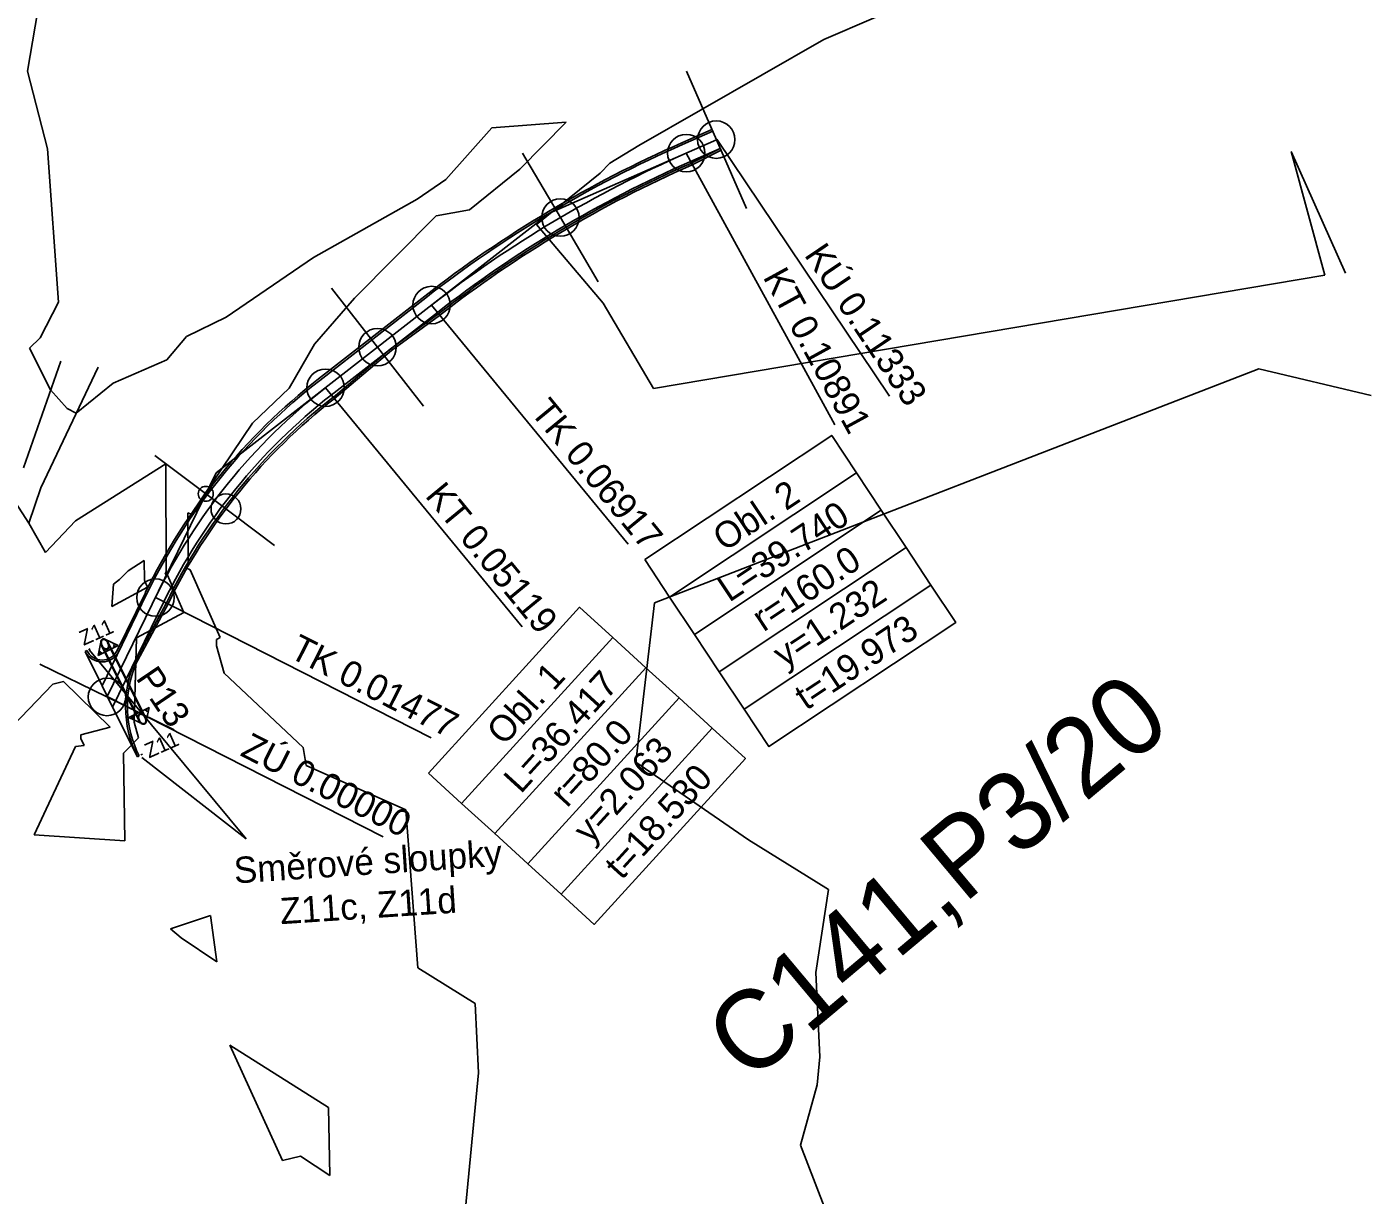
# Model space of a CAD drawing. Extents: x -549394 to -546608, y -1037055 to -1033629.
# Drawn here: x -547399.4 to -547219.7, y -1035351 to -1035194.8 of the extents above; entities that cross this region are included whole.
import ezdxf

# ---------------------------------------------------------------- set-up
doc = ezdxf.new("R2010")
doc.units = 0
for name, color, linetype in [('hlavni_vrst', 7, 'Continuous'), ('hrana_L', 7, 'Continuous'), ('norm_vrst', 7, 'Continuous'), ('POLYGONY_SITUACE_PO', 7, 'Continuous'), ('u_sirka_1_0m', 7, 'Continuous'), ('u_sirka_1_5m', 7, 'Continuous'), ('x_navrh_C141', 7, 'Continuous'), ('x_osa_C141', 7, 'Continuous'), ('x_popis_C141', 7, 'Continuous'), ('x_popis_oblouky_C141', 7, 'Continuous'), ('x_popis_pricne_rezy_C141', 7, 'Continuous'), ('x_popis_velky_C141', 7, 'Continuous'), ('x_propustek', 7, 'Continuous'), ('x_SDZ_C141', 7, 'Continuous')]:
    doc.layers.add(name, color=color, linetype=linetype)

msp = doc.modelspace()

# ---------------------------------------------------------------- linework, layer by layer
at = {"layer": 'hlavni_vrst'}
for p, q in [((-547292.9, -1035196.54), (-547278.84, -1035190.47)), ((-547317.64, -1035210.67), (-547292.9, -1035196.54)), ((-547321.49, -1035213.06), (-547317.64, -1035210.67)), ((-547230.43, -1035211.49), (-547225.89, -1035228.02)), ((-547223.15, -1035227.75), (-547230.43, -1035211.49)), ((-547322.82, -1035214.4), (-547321.49, -1035213.06)), ((-547331.31, -1035221.25), (-547322.82, -1035214.4)), ((-547322.39, -1035231.75), (-547331.31, -1035221.25)), ((-547225.89, -1035228.02), (-547315.67, -1035243.17)), ((-547315.67, -1035243.17), (-547322.39, -1035231.75)), ((-547315.53, -1035271.79), (-547234.74, -1035240.52)), ((-547234.74, -1035240.52), (-547219.72, -1035244.12)), ((-547318.05, -1035293.1), (-547315.53, -1035271.79)), ((-547302.95, -1035303.47), (-547318.05, -1035293.1)), ((-547292.27, -1035310.1), (-547302.95, -1035303.47)), ((-547293.96, -1035321.23), (-547292.27, -1035310.1)), ((-547293.45, -1035332.48), (-547293.96, -1035321.23)), ((-547293.8, -1035336.21), (-547293.45, -1035332.48)), ((-547296, -1035344.28), (-547293.8, -1035336.21)), ((-547283.79, -1035376.04), (-547296, -1035344.28))]:
    msp.add_line(p, q, dxfattribs=at)
at = {"layer": 'hrana_L'}
for p, q in [((-547394.93, -1035239.52), (-547399.91, -1035253.77)), ((-547389.94, -1035240.31), (-547397.57, -1035256.44)), ((-547397.57, -1035256.44), (-547399.19, -1035261.16))]:
    msp.add_line(p, q, dxfattribs=at)
at = {"layer": 'norm_vrst'}
for p, q in [((-547399.36, -1035200.76), (-547397.01, -1035186.98)), ((-547396.7, -1035211.13), (-547399.36, -1035200.76)), ((-547337.3, -1035208.32), (-547343.44, -1035215.22)), ((-547327.34, -1035207.57), (-547337.3, -1035208.32)), ((-547333.56, -1035213.85), (-547327.34, -1035207.57)), ((-547395.23, -1035231.65), (-547396.7, -1035211.13)), ((-547340.29, -1035219.28), (-547333.56, -1035213.85)), ((-547343.44, -1035215.22), (-547347.28, -1035217.87)), ((-547347.28, -1035217.87), (-547361.11, -1035225.68)), ((-547344.71, -1035220.1), (-547340.29, -1035219.28)), ((-547355.64, -1035231.11), (-547344.71, -1035220.1)), ((-547361.11, -1035225.68), (-547372.79, -1035233.63)), ((-547397.67, -1035236.39), (-547395.23, -1035231.65)), ((-547361.01, -1035237.24), (-547355.64, -1035231.11)), ((-547372.79, -1035233.63), (-547378.1, -1035236.22)), ((-547399.08, -1035237.78), (-547397.67, -1035236.39)), ((-547378.1, -1035236.22), (-547380.73, -1035239.35)), ((-547364.39, -1035243.11), (-547361.01, -1035237.24)), ((-547396.27, -1035243.34), (-547399.08, -1035237.78)), ((-547380.73, -1035239.35), (-547387.91, -1035242.46)), ((-547387.91, -1035242.46), (-547392.85, -1035246.47)), ((-547394.05, -1035245.85), (-547396.27, -1035243.34)), ((-547369.28, -1035247.8), (-547364.39, -1035243.11)), ((-547392.85, -1035246.47), (-547394.05, -1035245.85)), ((-547377.5, -1035259.97), (-547369.28, -1035247.8)), ((-547380.88, -1035253.24), (-547392.94, -1035260.85)), ((-547380.81, -1035267.64), (-547380.88, -1035253.24)), ((-547399.19, -1035261.16), (-547402.86, -1035255.5)), ((-547392.94, -1035260.85), (-547396.98, -1035265.09)), ((-547377.89, -1035266.54), (-547377.92, -1035259.76)), ((-547377.92, -1035259.76), (-547377.5, -1035259.97)), ((-547399.19, -1035261.16), (-547399.19, -1035261.16)), ((-547399.19, -1035261.16), (-547399.19, -1035261.16)), ((-547396.98, -1035265.09), (-547399.19, -1035261.16)), ((-547399.19, -1035261.16), (-547399.19, -1035261.16)), ((-547383.75, -1035266.15), (-547385.92, -1035267.52)), ((-547383.74, -1035268.75), (-547383.75, -1035266.15)), ((-547385.92, -1035267.52), (-547387.06, -1035268.71)), ((-547380.97, -1035267.96), (-547380.81, -1035267.64)), ((-547380.66, -1035268.12), (-547380.97, -1035267.96)), ((-547378.46, -1035273.09), (-547380.66, -1035268.12)), ((-547378.18, -1035267.11), (-547377.89, -1035266.54)), ((-547377.61, -1035267.4), (-547378.18, -1035267.11)), ((-547373.61, -1035276.45), (-547377.61, -1035267.4)), ((-547387.88, -1035269.32), (-547388.08, -1035272.29)), ((-547388.08, -1035272.29), (-547383.31, -1035269.73)), ((-547387.06, -1035268.71), (-547387.88, -1035269.32)), ((-547383.77, -1035268.8), (-547383.74, -1035268.75)), ((-547383.71, -1035268.83), (-547383.77, -1035268.8)), ((-547383.31, -1035269.73), (-547383.71, -1035268.83)), ((-547384.79, -1035276.49), (-547378.46, -1035273.09)), ((-547385.1, -1035287.74), (-547384.79, -1035276.49)), ((-547374.1, -1035277.54), (-547374.08, -1035276.7)), ((-547374.08, -1035276.7), (-547373.61, -1035276.45)), ((-547373.07, -1035281.22), (-547374.1, -1035277.54)), ((-547395.97, -1035282.66), (-547394.56, -1035282.33)), ((-547394.56, -1035282.33), (-547388.3, -1035288.42)), ((-547362.51, -1035291.15), (-547373.07, -1035281.22)), ((-547404.2, -1035291.19), (-547395.97, -1035282.66)), ((-547384.51, -1035289.83), (-547385.1, -1035287.74)), ((-547388.3, -1035288.42), (-547392.24, -1035289.43)), ((-547392.24, -1035289.43), (-547392.22, -1035289.95)), ((-547392.94, -1035290.99), (-547398.47, -1035302.8)), ((-547391.81, -1035290.88), (-547392.94, -1035290.99)), ((-547392.22, -1035289.95), (-547391.81, -1035290.88)), ((-547386.51, -1035291.88), (-547384.51, -1035289.83)), ((-547362.1, -1035293.55), (-547362.51, -1035291.15)), ((-547386.34, -1035303.6), (-547386.51, -1035291.88)), ((-547348.8, -1035299.47), (-547362.1, -1035293.55)), ((-547347.19, -1035320.57), (-547348.8, -1035299.47)), ((-547398.47, -1035302.8), (-547386.34, -1035303.6)), ((-547374.89, -1035313.57), (-547380.23, -1035315.38)), ((-547374.05, -1035319.8), (-547374.89, -1035313.57)), ((-547380.23, -1035315.38), (-547378.83, -1035316.58)), ((-547378.83, -1035316.58), (-547374.05, -1035319.8)), ((-547339.51, -1035325.35), (-547347.19, -1035320.57)), ((-547339.08, -1035334.62), (-547339.51, -1035325.35)), ((-547372.31, -1035330.92), (-547359.1, -1035339.24)), ((-547365.27, -1035346.33), (-547372.31, -1035330.92)), ((-547341.62, -1035361.33), (-547339.08, -1035334.62)), ((-547359.1, -1035339.24), (-547358.95, -1035348.33)), ((-547362.88, -1035345.77), (-547365.27, -1035346.33)), ((-547365.27, -1035346.33), (-547365.27, -1035346.33)), ((-547358.95, -1035348.33), (-547362.88, -1035345.77)), ((-547362.88, -1035345.77), (-547362.88, -1035345.77))]:
    msp.add_line(p, q, dxfattribs=at)
at = {"layer": 'POLYGONY_SITUACE_PO'}
for centre in [(-547307.28, -1035209.91), (-547311.29, -1035211.71), (-547345.34, -1035232.01), (-547359.52, -1035243.06), (-547382.26, -1035271.11), (-547388.74, -1035284.39)]:
    msp.add_circle(centre, 2.5, dxfattribs=at)
at = {"layer": 'u_sirka_1_0m'}
for centre in [(-547328.12, -1035220.32), (-547352.57, -1035237.65)]:
    msp.add_circle(centre, 2.5, dxfattribs=at)
at = {"layer": 'u_sirka_1_5m'}
for centre, radius in [((-547375.53, -1035257.24), 1), ((-547372.83, -1035259.26), 2)]:
    msp.add_circle(centre, radius, dxfattribs=at)
at = {"layer": 'x_navrh_C141'}
for p, q in [((-547311.9, -1035210.34), (-547307.85, -1035208.56)), ((-547311.8, -1035210.57), (-547307.75, -1035208.79)), ((-547310.79, -1035212.86), (-547306.75, -1035211.08)), ((-547310.7, -1035213.08), (-547306.75, -1035211.08)), ((-547310.59, -1035213.3), (-547306.64, -1035211.31)), ((-547360.45, -1035241.88), (-547346.26, -1035230.83)), ((-547360.29, -1035242.08), (-547346.11, -1035231.03)), ((-547358.76, -1035244.05), (-547344.57, -1035233)), ((-547344.42, -1035233.19), (-547350.87, -1035237.9)), ((-547344.27, -1035233.39), (-547350.71, -1035238.1)), ((-547358.52, -1035244.35), (-547350.87, -1035237.9)), ((-547358.36, -1035244.54), (-547350.71, -1035238.1)), ((-547389.4, -1035282.89), (-547383.39, -1035270.56)), ((-547388, -1035285.73), (-547381.14, -1035271.66)), ((-547387.38, -1035278.18), (-547383.61, -1035270.45)), ((-547380.8, -1035271.82), (-547385.52, -1035280.64)), ((-547380.57, -1035271.94), (-547381.77, -1035274.18)), ((-547381.77, -1035274.18), (-547384.91, -1035280.04)), ((-547391.42, -1035278.19), (-547391.65, -1035278.3)), ((-547391.65, -1035278.3), (-547389.4, -1035282.89)), ((-547389.4, -1035282.89), (-547388, -1035285.73)), ((-547384.67, -1035292.37), (-547384.44, -1035292.26))]:
    msp.add_line(p, q, dxfattribs=at)
msp.add_lwpolyline([(-547388, -1035285.73), (-547384.67, -1035292.37)], dxfattribs=at)
for centre, radius, start, end in [((-547247, -1035358.23), 161.5, 113.6926, 127.9233), ((-547247, -1035358.23), 161.25, 113.6926, 127.9233), ((-547247, -1035358.23), 158.75, 113.6926, 127.9233), ((-547247, -1035358.23), 158.51, 113.6926, 127.9233), ((-547247, -1035358.23), 158.26, 113.6901, 127.9246), ((-547310.36, -1035306.17), 81.5, 127.9233, 154.0053), ((-547310.36, -1035306.17), 81.25, 127.9233, 154.0053), ((-547310.36, -1035306.17), 78.75, 127.9233, 154.0053), ((-547310.36, -1035306.17), 78.37, 127.9233, 154.0053), ((-547310.36, -1035306.17), 78.12, 127.9198, 154.0088), ((-547389.4, -1035277.2), 2.5, 206.1096, 334.0053), ((-547389.4, -1035277.2), 2.25, 206.1096, 334.0053), ((-547371.26, -1035285.63), 15, 154.0053, 206.694), ((-547371.26, -1035285.63), 14.75, 157.7223, 206.694)]:
    msp.add_arc(centre, radius, start, end, dxfattribs=at)
at = {"layer": 'x_osa_C141'}
for points in [[(-547329.58, -1035219.74), (-547307.25, -1035209.94)], [(-547374.14, -1035254.45), (-547329.58, -1035219.74)], [(-547388.7, -1035284.31), (-547374.14, -1035254.45)]]:
    msp.add_lwpolyline(points, dxfattribs=at)
for centre, radius, start, end in [((-547247, -1035358.23), 160, 113.6926, 127.9233), ((-547310.36, -1035306.17), 80, 127.9233, 154.0053)]:
    msp.add_arc(centre, radius, start, end, dxfattribs=at)
at = {"layer": 'x_popis_oblouky_C141'}
for points in [[(-547284.12, -1035244.19), (-547307.21, -1035209.86)], [(-547291.44, -1035248.01), (-547311.29, -1035211.71)], [(-547319.06, -1035263.97), (-547345.34, -1035232.01)], [(-547333.24, -1035275.02), (-547359.52, -1035243.06)], [(-547345.39, -1035289.87), (-547382.26, -1035271.11)], [(-547351.82, -1035303.07), (-547388.7, -1035284.31)]]:
    msp.add_lwpolyline(points, dxfattribs=at)
for points in [[(-547316.83, -1035266.03), (-547291.84, -1035249.44), (-547288.52, -1035254.43), (-547313.52, -1035271.03)], [(-547313.52, -1035271.03), (-547288.52, -1035254.43), (-547285.21, -1035259.43), (-547310.2, -1035276.03)], [(-547310.2, -1035276.03), (-547285.21, -1035259.43), (-547281.89, -1035264.43), (-547306.88, -1035281.03)], [(-547306.88, -1035281.03), (-547281.89, -1035264.43), (-547278.57, -1035269.43), (-547303.56, -1035286.03)], [(-547303.56, -1035286.03), (-547278.57, -1035269.43), (-547275.25, -1035274.43), (-547300.24, -1035291.02)], [(-547345.76, -1035294.57), (-547325.55, -1035272.4), (-547321.12, -1035276.44), (-547341.33, -1035298.61)], [(-547341.33, -1035298.61), (-547321.12, -1035276.44), (-547316.68, -1035280.48), (-547336.89, -1035302.65)], [(-547336.89, -1035302.65), (-547316.68, -1035280.48), (-547312.25, -1035284.52), (-547332.46, -1035306.7)], [(-547332.46, -1035306.7), (-547312.25, -1035284.52), (-547307.81, -1035288.57), (-547328.02, -1035310.74)], [(-547328.02, -1035310.74), (-547307.81, -1035288.57), (-547303.38, -1035292.61), (-547323.59, -1035314.78)]]:
    msp.add_lwpolyline(points, close=True, dxfattribs=at)
at = {"layer": 'x_popis_pricne_rezy_C141'}
for points in [[(-547311.27, -1035200.78), (-547307.25, -1035209.94), (-547303.23, -1035219.09)], [(-547333.19, -1035211.7), (-547328.12, -1035220.32), (-547323.05, -1035228.93)], [(-547358.72, -1035229.76), (-547352.57, -1035237.65), (-547346.43, -1035245.54)], [(-547382.33, -1035252.13), (-547374.33, -1035258.14), (-547366.33, -1035264.14)], [(-547397.72, -1035280), (-547388.74, -1035284.39), (-547379.75, -1035288.77)]]:
    msp.add_lwpolyline(points, dxfattribs=at)
at = {"layer": 'x_propustek'}
for p, q in [((-547389.94, -1035278.85), (-547389.51, -1035276.82)), ((-547389.13, -1035276.63), (-547389.51, -1035276.82)), ((-547389.13, -1035276.63), (-547387.26, -1035277.51)), ((-547383.66, -1035287.15), (-547388.65, -1035277.15)), ((-547383.59, -1035287.11), (-547388.58, -1035277.11)), ((-547389.94, -1035278.85), (-547387.26, -1035277.51)), ((-547389.52, -1035278.64), (-547389.69, -1035278.28)), ((-547389.61, -1035278.68), (-547389.69, -1035278.5)), ((-547389.43, -1035278.59), (-547389.52, -1035278.42)), ((-547384.47, -1035287.55), (-547389.46, -1035277.55)), ((-547384.4, -1035287.52), (-547389.39, -1035277.52)), ((-547387.68, -1035277.72), (-547387.86, -1035277.36)), ((-547387.77, -1035277.77), (-547387.86, -1035277.59)), ((-547387.59, -1035277.68), (-547387.68, -1035277.5)), ((-547383.11, -1035285.81), (-547385.8, -1035287.15)), ((-547383.62, -1035286.07), (-547383.53, -1035286.25)), ((-547383.11, -1035285.81), (-547383.54, -1035287.84)), ((-547383.53, -1035286.02), (-547383.36, -1035286.38)), ((-547383.44, -1035285.98), (-547383.36, -1035286.16)), ((-547383.92, -1035288.03), (-547385.8, -1035287.15)), ((-547385.46, -1035286.99), (-547385.37, -1035287.17)), ((-547385.37, -1035286.94), (-547385.2, -1035287.3)), ((-547385.28, -1035286.9), (-547385.19, -1035287.08)), ((-547383.92, -1035288.03), (-547383.54, -1035287.84))]:
    msp.add_line(p, q, dxfattribs=at)
for points in [[(-547389.36, -1035276.66), (-547389.37, -1035276.67), (-547389.38, -1035276.67), (-547389.41, -1035276.69), (-547389.42, -1035276.7), (-547389.46, -1035276.74), (-547389.48, -1035276.76), (-547389.53, -1035276.85), (-547389.56, -1035276.92), (-547389.58, -1035277.09), (-547389.57, -1035277.18), (-547389.53, -1035277.37), (-547389.5, -1035277.46), (-547389.41, -1035277.64), (-547389.36, -1035277.72), (-547389.23, -1035277.86), (-547389.16, -1035277.92), (-547389.01, -1035278.01), (-547388.94, -1035278.03), (-547388.86, -1035278.04), (-547388.84, -1035278.04), (-547388.81, -1035278.04), (-547388.79, -1035278.04), (-547388.74, -1035278.03), (-547388.71, -1035278.02), (-547388.68, -1035278)], [(-547389.32, -1035276.73), (-547389.34, -1035276.74), (-547389.36, -1035276.75), (-547389.4, -1035276.79), (-547389.42, -1035276.81), (-547389.45, -1035276.85), (-547389.46, -1035276.88), (-547389.48, -1035276.94), (-547389.49, -1035276.98), (-547389.5, -1035277.05), (-547389.5, -1035277.09), (-547389.49, -1035277.17), (-547389.49, -1035277.22), (-547389.46, -1035277.34), (-547389.43, -1035277.43), (-547389.35, -1035277.6), (-547389.3, -1035277.68), (-547389.21, -1035277.78), (-547389.18, -1035277.81), (-547389.11, -1035277.86), (-547389.08, -1035277.88), (-547389.02, -1035277.92), (-547388.99, -1035277.93), (-547388.92, -1035277.95), (-547388.89, -1035277.96), (-547388.84, -1035277.97), (-547388.81, -1035277.96), (-547388.76, -1035277.96), (-547388.74, -1035277.95), (-547388.7, -1035277.93), (-547388.68, -1035277.91), (-547388.64, -1035277.88), (-547388.62, -1035277.86), (-547388.59, -1035277.81), (-547388.58, -1035277.78), (-547388.56, -1035277.72), (-547388.55, -1035277.69), (-547388.54, -1035277.61), (-547388.54, -1035277.57), (-547388.55, -1035277.49), (-547388.55, -1035277.45), (-547388.58, -1035277.32), (-547388.61, -1035277.23), (-547388.69, -1035277.06), (-547388.75, -1035276.99), (-547388.83, -1035276.89), (-547388.86, -1035276.86), (-547388.93, -1035276.81), (-547388.96, -1035276.78), (-547389.02, -1035276.75), (-547389.06, -1035276.73), (-547389.12, -1035276.71), (-547389.15, -1035276.7), (-547389.2, -1035276.7), (-547389.23, -1035276.7), (-547389.28, -1035276.71), (-547389.3, -1035276.72), (-547389.32, -1035276.73)], [(-547388.68, -1035278), (-547388.67, -1035278), (-547388.66, -1035277.99), (-547388.63, -1035277.97), (-547388.62, -1035277.96), (-547388.58, -1035277.93), (-547388.56, -1035277.9), (-547388.51, -1035277.81), (-547388.49, -1035277.74), (-547388.46, -1035277.57), (-547388.47, -1035277.48), (-547388.51, -1035277.3), (-547388.54, -1035277.2), (-547388.63, -1035277.02), (-547388.68, -1035276.94), (-547388.81, -1035276.8), (-547388.88, -1035276.74), (-547389.03, -1035276.66), (-547389.1, -1035276.63), (-547389.18, -1035276.63), (-547389.2, -1035276.62), (-547389.23, -1035276.63), (-547389.25, -1035276.63), (-547389.3, -1035276.64), (-547389.33, -1035276.65), (-547389.36, -1035276.66)], [(-547384.37, -1035286.66), (-547384.38, -1035286.67), (-547384.39, -1035286.67), (-547384.42, -1035286.69), (-547384.43, -1035286.7), (-547384.47, -1035286.73), (-547384.49, -1035286.76), (-547384.54, -1035286.85), (-547384.57, -1035286.92), (-547384.59, -1035287.09), (-547384.58, -1035287.18), (-547384.54, -1035287.36), (-547384.51, -1035287.46), (-547384.42, -1035287.64), (-547384.37, -1035287.72), (-547384.24, -1035287.86), (-547384.17, -1035287.92), (-547384.02, -1035288.01), (-547383.95, -1035288.03), (-547383.87, -1035288.04), (-547383.85, -1035288.04), (-547383.82, -1035288.04), (-547383.8, -1035288.04), (-547383.75, -1035288.03), (-547383.72, -1035288.02), (-547383.69, -1035288)], [(-547383.73, -1035287.94), (-547383.71, -1035287.93), (-547383.69, -1035287.91), (-547383.65, -1035287.88), (-547383.63, -1035287.86), (-547383.6, -1035287.81), (-547383.59, -1035287.78), (-547383.57, -1035287.72), (-547383.56, -1035287.69), (-547383.55, -1035287.61), (-547383.55, -1035287.57), (-547383.56, -1035287.49), (-547383.56, -1035287.45), (-547383.59, -1035287.32), (-547383.62, -1035287.23), (-547383.7, -1035287.06), (-547383.75, -1035286.98), (-547383.84, -1035286.89), (-547383.87, -1035286.86), (-547383.94, -1035286.81), (-547383.97, -1035286.78), (-547384.03, -1035286.75), (-547384.07, -1035286.73), (-547384.13, -1035286.71), (-547384.16, -1035286.7), (-547384.21, -1035286.7), (-547384.24, -1035286.7), (-547384.29, -1035286.71), (-547384.31, -1035286.71), (-547384.35, -1035286.74), (-547384.37, -1035286.75), (-547384.41, -1035286.78), (-547384.43, -1035286.8), (-547384.46, -1035286.85), (-547384.47, -1035286.88), (-547384.49, -1035286.94), (-547384.5, -1035286.98), (-547384.51, -1035287.05), (-547384.51, -1035287.09), (-547384.5, -1035287.17), (-547384.5, -1035287.21), (-547384.47, -1035287.34), (-547384.44, -1035287.43), (-547384.36, -1035287.6), (-547384.31, -1035287.68), (-547384.22, -1035287.77), (-547384.19, -1035287.8), (-547384.12, -1035287.86), (-547384.09, -1035287.88), (-547384.03, -1035287.92), (-547383.99, -1035287.93), (-547383.93, -1035287.95), (-547383.9, -1035287.96), (-547383.85, -1035287.96), (-547383.82, -1035287.96), (-547383.77, -1035287.95), (-547383.75, -1035287.95), (-547383.73, -1035287.94)], [(-547383.69, -1035288), (-547383.68, -1035288), (-547383.67, -1035287.99), (-547383.64, -1035287.97), (-547383.63, -1035287.96), (-547383.59, -1035287.93), (-547383.57, -1035287.9), (-547383.52, -1035287.81), (-547383.49, -1035287.74), (-547383.47, -1035287.57), (-547383.48, -1035287.48), (-547383.52, -1035287.3), (-547383.55, -1035287.2), (-547383.64, -1035287.02), (-547383.69, -1035286.94), (-547383.82, -1035286.8), (-547383.89, -1035286.74), (-547384.04, -1035286.66), (-547384.11, -1035286.63), (-547384.19, -1035286.62), (-547384.21, -1035286.62), (-547384.24, -1035286.62), (-547384.26, -1035286.63), (-547384.31, -1035286.63), (-547384.34, -1035286.64), (-547384.37, -1035286.66)]]:
    msp.add_open_spline(points, degree=3, dxfattribs=at)
at = {"layer": 'x_SDZ_C141'}
for p, q in [((-547391.2, -1035278.07), (-547390.98, -1035277.96)), ((-547384.22, -1035292.14), (-547384, -1035292.03))]:
    msp.add_line(p, q, dxfattribs=at)
for points in [[(-547391.09, -1035278.14), (-547370.11, -1035303.36)], [(-547384.08, -1035292.47), (-547370.11, -1035303.36)]]:
    msp.add_lwpolyline(points, dxfattribs=at)

# ---------------------------------------------------------------- texts
at = {"layer": 'x_popis_C141'}
msp.add_text('P13', height=3.5, rotation=304.13, dxfattribs=at).set_placement((-547384.98, -1035281.87))
at = {"layer": 'x_popis_oblouky_C141'}
for s, rotation, p in [('KÚ 0.11333', 303.9359, (-547295.6, -1035225.32)), ('KT 0.10891', 298.6724, (-547301.1, -1035228.27)), ('TK 0.06917', 309.4375, (-547332.25, -1035246.35)), ('KT 0.05119', 309.4375, (-547346.31, -1035257.55)), ('Obl. 2', 33.6097, (-547306.2, -1035265.04)), ('L=39.740', 33.6097, (-547305.55, -1035271.81)), ('r=160.0', 33.6097, (-547300.96, -1035275.76)), ('y=1.232', 33.6097, (-547298.18, -1035280.58)), ('t=19.973', 33.6097, (-547295.25, -1035286.26)), ('TK 0.01477', 333.0352, (-547364.53, -1035279.01)), ('Obl. 1', 47.6745, (-547335.68, -1035291.02)), ('L=36.417', 47.6745, (-547333.41, -1035297.43)), ('r=80.0', 47.6745, (-547327.22, -1035299.29)), ('ZÚ 0.00000', 333.0352, (-547371.07, -1035292.15)), ('y=2.063', 47.6745, (-547324.13, -1035304.15)), ('t=18.530', 47.6745, (-547319.91, -1035308.95))]:
    msp.add_text(s, height=3.5, rotation=rotation, dxfattribs=at).set_placement(p)
at = {"layer": 'x_popis_velky_C141'}
msp.add_text('C141,P3/20', height=10.5, rotation=39.9525, dxfattribs=at).set_placement((-547302.89, -1035336.17))
at = {"layer": 'x_SDZ_C141'}
for s, height, rotation, p in [('Z11', 2, 23.9554, (-547391.88, -1035277.57)), ('Z11', 2, 23.9554, (-547383.14, -1035292.62)), ('Směrové sloupky', 3.5, 3.7669, (-547371.66, -1035309.31)), ('Z11c, Z11d', 3.5, 3.7669, (-547365.5, -1035314.76))]:
    msp.add_text(s, height=height, rotation=rotation, dxfattribs=at).set_placement(p)

doc.saveas('drawing.dxf')
